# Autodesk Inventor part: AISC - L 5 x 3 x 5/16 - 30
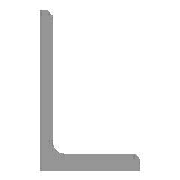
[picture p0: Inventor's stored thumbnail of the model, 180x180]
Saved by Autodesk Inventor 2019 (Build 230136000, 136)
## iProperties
Created: 2019-01
Part Number: AISC - L 5 x 3 x 5/16 - 30
Material: Steel, Mild
Description: Angle Steel
Document SubType Name: Modeling
Standard: ANSI
Designer: ElizabethC
Standards Organization: ANSI
Language: en-US
Size Designation: L 5 x 3 x 5/16
Categories: <MemberInstance><Categories><Category DisplayName="Structural Shapes" InternalName="089c4875-fa83-4c05-b084-43b9cc11f5ed" Mnemonic="GRDR"><CategoryParameter Dis
Stock Number: L 5 x 3 x 5/16
Mass: 8334.49 g
Surface Area: 2721.47 cm^2
Volume: 1061.72 cm^3
Density: 7.85 g/cm^3
Appearance: Semi-Polished
IsCustomPart: 1
_CCFamilyMember: 39
_CCFamilyDisplayName: ANSI L (Unequal angles) - Angle Steel — Sizes in parentheses have been withdrawn
_FrameMemberDoc: Frame Member File
_Version: 15.0.0
_GetPNFromCC: 1
Author: ElizabethC
G_L: 30.000 in
G_W: 3.000 in
G_H: 5.000 in
+E36162CD-4C8B-4080-B5B9-4A733B6C026D+CUTDETAIL1: Miter 45.00 deg
+C7612AE9-03D0-406D-AB52-40E6B7CC26CE+CUTDETAIL2: Miter 45.00 deg
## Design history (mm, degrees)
node "Start plane"
node "End plane"
sketch "Sketch"
  geometry: L1 (70.612, 7.95)-(19.126, 7.95); L2 (0, 0)-(76.2, 0); L3 (76.2, 0)-(76.2, 2.362); L4 (-7.041, 0)-(21.538, 0); L5 (7.95, 19.126)-(7.95, 121.412); L6 (0, 127)-(0, 0); L7 (2.362, 127)-(0, 127); L8 (0, -8.041)-(0, 34.538); L9 (0, 155.397)-(0, -35.281) reference; L10 (-23.921, 0)-(94.237, 0) reference; A1 r 11.176 centre (19.126, 19.126) between (7.95, 19.126) and (19.126, 7.95); A2 r 5.588 centre (70.612, 2.362) between (76.2, 2.362) and (70.612, 7.95); A3 r 5.588 centre (2.362, 121.412) between (7.95, 121.412) and (2.362, 127); 3 further points
  constraints: 16 end point, 6 point on circle, 6 point on line, 6 tangent, 3 centre point, 2 collinear, 2 parallel, 1 equal radius
  dimensions: "d12" = 7.9502 distance between parallel lines of L5 L6 (= G_T); "d13" = 127 distance of L6.start L2.start (= G_H); "d14" = 76.2 distance of L2.start L2.end (= G_W); "d15" = 0 distance between parallel lines of L4 L2 (computed from ex); "d16" = 7.9502 distance between parallel lines of L2 L1 (= G_T); "d17" = 0 distance between parallel lines of L8 L6 (computed from ey); "d18" = 11.176 radius of A1 (= G_IR); "d19" = 5.588 radius of A2 (= G_ER)
extrude "Body" new body sketch "Sketch" stored distance "d4" = 762 (= G_L); taper "d5" = 0 deg
node "Driven Length"
  sketch "Sketch3"
    geometry: L1 (0, 0)-(10, 0) reference
    constraints: 2 end point, 1 horizontal
  workplane "Work Plane3"
  sketch "Sketch4"
    geometry: L1 (-2, 0)-(12, 0) reference; L2 (-2, 762)-(12, 762) reference
    dimensions: "d23" = 762 distance between parallel lines of L1 L2 (derived)
workplane "Work Plane4"
split "Split1"
workplane "Work Plane5"
split "Split2"
body "Solid1"
other parameters: "G_W" = 76.2 [user parameter; used in 1 equation term], "G_H" = 127 [user parameter; used in 1 equation term], "G_T" = 7.9502 [user parameter; used in 2 equation terms], "G_ER" = 5.588 [user parameter; used in 1 equation term], "G_IR" = 11.176 [user parameter; used in 1 equation term], "G_L" = 762 (= d23) [user parameter; used in 1 equation term], "ex" = 0 [user parameter; used in 1 equation term], "ey" = 0 [user parameter; used in 1 equation term], "G_OFFSET_START" = 0 [user parameter; used in 1 equation term], "G_OFFSET_END" = 0 [user parameter; used in 1 equation term], "d20" = 0 (computed from G_OFFSET_START), "d21" = 762 (= G_OFFSET_END + B_L), "B_L" = 762 [user parameter; used in 1 equation term], "d22" = 90 deg, "MAS" = 1.22029 [user parameter]
